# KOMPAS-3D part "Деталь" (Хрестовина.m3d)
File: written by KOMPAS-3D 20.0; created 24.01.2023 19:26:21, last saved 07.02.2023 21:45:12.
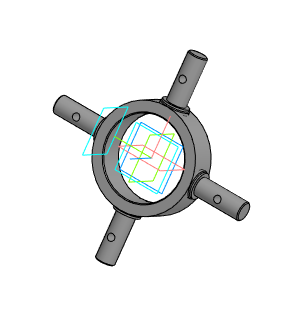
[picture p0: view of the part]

Document properties: Автор: User; Полное имя файла: C:\Users\User\Desktop\Хрестовина.m3d

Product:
- Part/product: Деталь
    Масса: 1.5337
  - Body: Тело 2
      Масса: 0.607067
  - Body: Тело 1
      Масса: 0.926632

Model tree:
1. Эскиз:1
2. Элемент выдавливания:1
     Расстояние 1 = 16; Расстояние 2 = 16
3. Эскиз:2
4. Элемент выдавливания:2
     Расстояние 1 = 16; Расстояние 2 = 16
5. Фаска:1  (with: Элемент выдавливания:2)
     Угол = 45; Длина 1 = 1; Длина 2 = 1
6. Смещенная плоскость:1
     Расстояние = 55
7. Эскиз:3
8. Элемент выдавливания:3
     Расстояние 1 = 55
9. Эскиз:4
10. Элемент выдавливания:5
     Расстояние 1 = 1; Расстояние 2 = 3
11. Эскиз:5
12. Элемент вращения:1
     Угол 1 = 360
13. Эскиз:6  (with: Элемент выдавливания:5, Элемент вращения:1)
14. Элемент выдавливания:6
     Расстояние 1 = 2
15. Фаска:2  (with: Элемент выдавливания:3)
     Угол = 45; Длина 1 = 1; Длина 2 = 1
16. Массив вдоль кривой:1
17. Экземпляр ( 1 )
18. Экземпляр ( 2 )  (with: Элемент выдавливания:5, Смещенная плоскость:1, Эскиз:4, Элемент вращения:1, Эскиз:5, Элемент выдавливания:6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)
19. Экземпляр ( 3 )  (with: Элемент выдавливания:5, Смещенная плоскость:1, Эскиз:4, Элемент вращения:1, Эскиз:5, Элемент выдавливания:6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)
20. Экземпляр ( 4 )  (with: Элемент выдавливания:5, Смещенная плоскость:1, Эскиз:4, Элемент вращения:1, Эскиз:5, Элемент выдавливания:6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)
     Шаг = 10
21. Смещенная плоскость:2
     Расстояние = 10
22. Эскиз:7
23. Элемент выдавливания:7
     Расстояние 2 = 26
